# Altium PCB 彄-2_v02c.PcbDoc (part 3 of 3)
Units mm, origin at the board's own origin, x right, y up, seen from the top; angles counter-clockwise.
Board outline 115 x 70 mm, 4 copper layers (Top Layer, Mid-Layer 1, Mid-Layer 2, Bottom Layer), stack 1.49 mm thick; 312 components, 169 nets, 916 pads, 492 vias.
Unrouted connection lines stored in the file: 1.
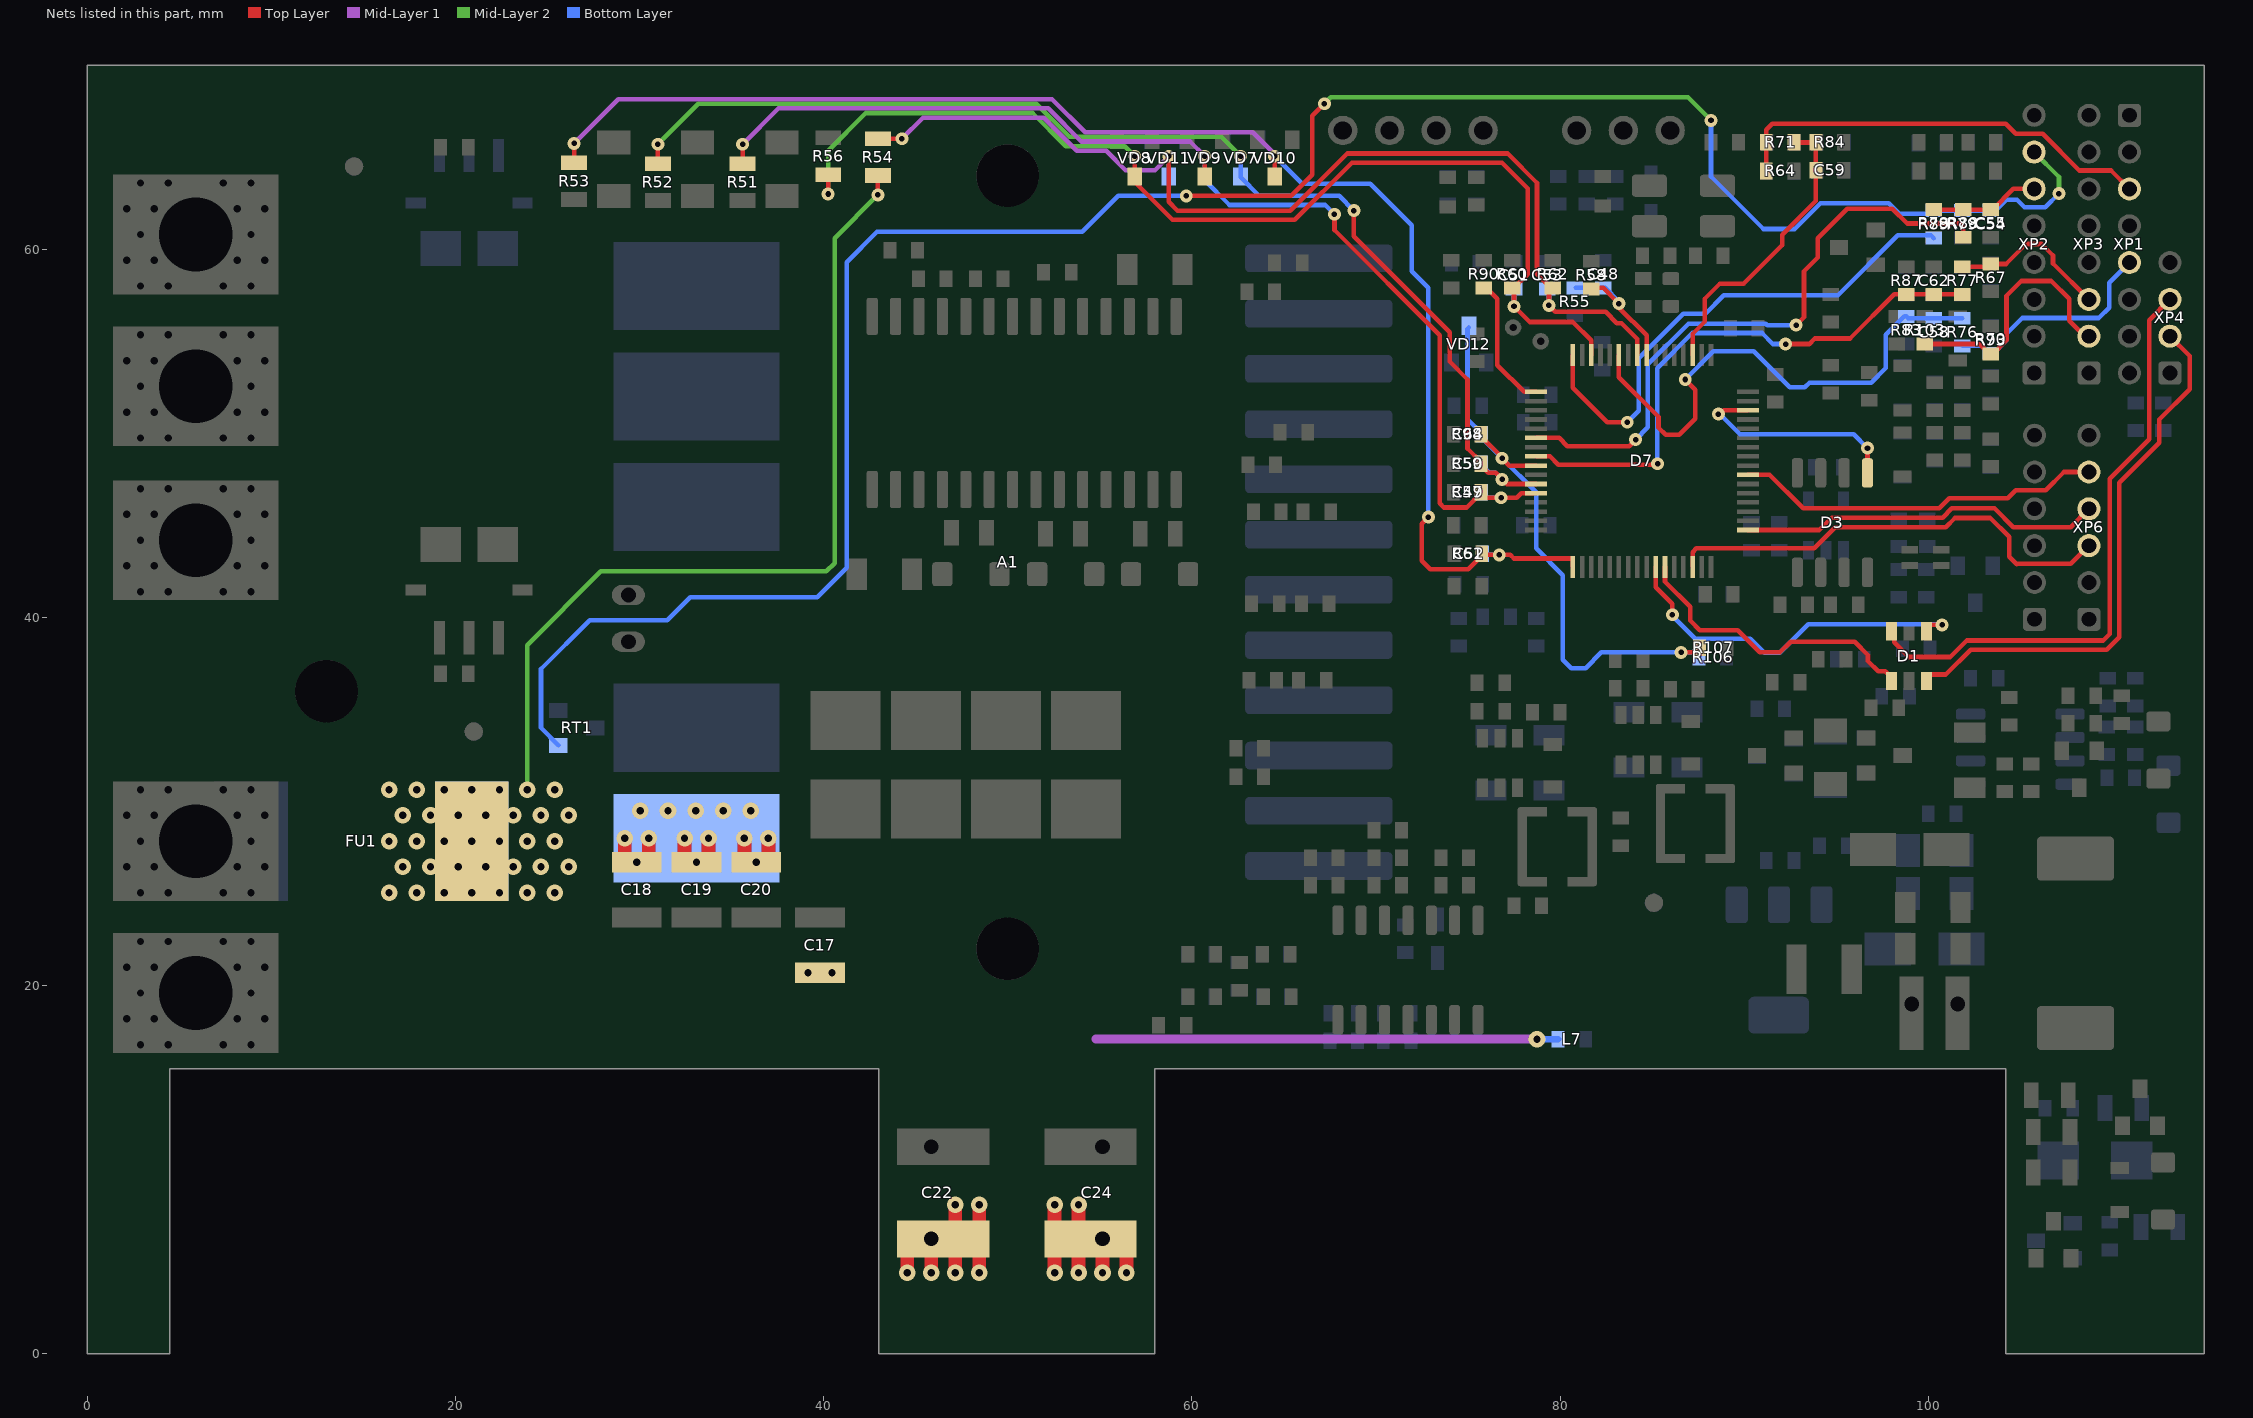
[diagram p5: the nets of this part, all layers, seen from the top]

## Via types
v1: diameter 0.9, hole 0.4, Top Layer to Bottom Layer, 233 vias
v2: diameter 0.7, hole 0.3, Top Layer to Bottom Layer, tented both sides, 184 vias
v3: diameter 0.9, hole 0.4, Top Layer to Bottom Layer, tented both sides, 50 vias
v4: diameter 0.9, hole 0.4, Top Layer to Bottom Layer, tented bottom, 25 vias

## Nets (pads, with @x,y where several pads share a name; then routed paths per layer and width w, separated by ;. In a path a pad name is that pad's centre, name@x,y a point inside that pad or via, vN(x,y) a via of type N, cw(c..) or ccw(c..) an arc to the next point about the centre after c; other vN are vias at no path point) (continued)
SPD2_COS: R93.2 R103.2 XP3.2 | length 13.9
  Top Layer w0.25: R103.2@99.8,54.85 102.8,54.85 103.35,54.3 R93.2@103.4,54.3 103.5,54.3 104.25,55.05 104.25,57.475 105.05,58.275 106.675,58.275 107.65,57.3 107.65,56.125 XP3.2@108.5,55.275
SPD_SW: R64.2 R71.1 XP1.3 | length 23.6
  Top Layer w0.25: R64.2@91.2,64.25 R71.1@91.2,65.8 91.2,66.5 91.525,66.825 104.2,66.825 104.75,66.275 106.209,66.275 108.209,64.275 109.925,64.275 XP1.3@110.925,63.275
SPD_SWU: C59.2 D7.3 R71.2 R84.2 | length 16.3
  Top Layer w0.24: D7.3@87.2,54.25 87.2,55.4 87.85,56.05 87.85,57.3 88.685,58.135 89.985,58.135 92.075,60.225 92.075,60.675
  Top Layer w0.25: 92.075,60.675 92.075,60.796 93.9,62.621 C59.2@93.9,64.3 R84.2@93.9,65.8 R71.2@92.7,65.8
TCK: D7.49 XP6.4 | length 19.8
  Top Layer w0.25: D7.49@90.2,44.75 94.075,44.75 94.75,45.425 100.783,45.425 101.283,45.925 103.6,45.925 104.615,44.91 107.735,44.91 XP6.4@108.725,45.9
TDO: D7.55 XP6.5 | length 19.9
  Top Layer w0.25: D7.55@90.2,47.75 91.375,47.75 93.2,45.925 100.59,45.925 101.14,46.475 104.325,46.475 104.76,46.91 106.385,46.91 107.375,47.9 XP6.5@108.5,47.9
THROTTLE: C58.2 D7.11 R76.2 R83.2 | length 28.9
  Top Layer w0.25: D7.11@83.2,54.25 83.2,53.05 85.35,50.9 85.35,50.3 85.735,49.915 86.465,49.915 87.35,50.8 87.35,52.375 v2(86.8,52.925)
  Bottom Layer w0.25: v2(86.8,52.925) 88.325,54.45 90.524,54.45 92.474,52.5 93.3,52.5 93.55,52.75 96.9,52.75 97.7,53.55 97.7,55.35 98.7,56.35 R83.2@98.8,56.35 98.9,56.25 C58.2@100.3,56.25 R76.2@101.85,56.25
THROTTLE-IN: R70.2 R76.1 XP1.5 | length 12.3
  Bottom Layer w0.25: R76.1@101.85,54.75 102.9,54.75 103.3,54.35 R70.2@103.4,54.35 103.55,54.35 104.25,55.05 104.25,55.4 105.115,56.265 109.265,56.265 109.825,56.825 109.825,58.175 XP1.5@110.925,59.275
TMOTOR1+: C55.2 R78.1 R88.2 XP2.6 | length 5.9
  Top Layer w0.25: R78.1@100.3,62.15 R88.2@101.9,62.15 C55.2@103.4,62.15 103.5,62.15 104.625,63.275 XP2.6@105.75,63.275
TMOTOR1U: D7.22 R88.1 | length 33.7
  Top Layer w0.25: D7.22@78.7,49.75 79.95,49.75 80.4,49.3 83.75,49.3 v2@84,49.55 ; v2(92.825,55.875) 93.25,56.3 93.25,58.8 94,59.55 94,60.6 95.6,62.2 98.05,62.2 98.85,61.4 101.75,61.4 101.9,61.25 R88.1@101.9,60.65
  Bottom Layer w0.25: v2(84.109,49.659) 84.775,50.325 84.775,53.745 86.98,55.95 91.175,55.95 91.25,55.875 v2(92.825,55.875)
TMS: D7.46 XP6.3 | length 25.2
  Top Layer w0.25: D7.46@87.2,42.75 87.2,43.55 87.4,43.75 93.8,43.75 94.95,44.9 100.951,44.9 101.451,45.4 103.375,45.4 104.4,44.375 104.4,43.3 104.8,42.9 104.81,42.91 107.735,42.91 XP6.3@108.725,43.9
TORQUE-IN: R67.2 R77.1 XP3.3 | length 8.7
  Top Layer w0.25: R77.1@101.85,59.05 R67.2@103.25,59.05 ; R67.2@103.4,59.2 104.225,59.2 105.31,60.285 106.15,60.285 106.775,59.66 106.775,59.225 XP3.3@108.725,57.275
TORQUESNS: C62.2 D7.24 R77.2 R87.2 | length 30.7
  Top Layer w0.25: D7.24@78.7,48.75 79.455,48.75 79.905,48.3 85.25,48.3 v2(85.3,48.35) ; v2(92.25,54.85) 93.543,54.85 93.843,55.15 95.75,55.15 98.15,57.55 R87.2@98.8,57.55 R77.2@101.85,57.55
  Bottom Layer w0.25: v2(85.3,48.35) 85.275,48.375 85.275,53.538 87.187,55.45 90.968,55.45 91.568,54.85 v2(92.25,54.85)
TPM1ORM2+: C54.2 R79.1 R89.2 RT1.1 XP2.7 | length 120.6
  Top Layer w0.25: v2(59.7,62.9) 65.4,62.9 66.55,64.05 66.55,67.25 v2(67.2,67.9)
  Mid-Layer 2 w0.25: v2(67.2,67.9) 67.55,68.25 86.95,68.25 v2(88.2,67) ; XP2.7@105.75,65.275 107.1,63.925 v2(107.1,63.025)
  Bottom Layer w0.25: RT1.1@25.6,33.05 24.65,34 24.65,37.2 27.3,39.85 31.5,39.85 32.75,41.1 39.65,41.1 41.25,42.7 41.25,59.3 42.9,60.95 54.05,60.95 56,62.9 v2(59.7,62.9) ; v2(88.2,67) 88.2,63.95 91.05,61.1 92.75,61.1 94.15,62.5 97.85,62.5 98.425,61.925 100.125,61.925 R89.2@100.3,62.1 R79.1@101.85,62.1 C54.2@103.4,62.1 103.639,62.1 104.229,62.69 104.821,62.69 105.226,62.285 106.36,62.285 v2(107.1,63.025)
TPM1ORM2U: D7.16 R89.1 | length 28.1
  Top Layer w0.25: D7.16@80.7,54.25 80.7,52.468 82.568,50.6 v2(83.65,50.6)
  Bottom Layer w0.25: v2(83.65,50.6) 84.275,51.225 84.275,54.075 86.7,56.5 87.9,56.5 88.9,57.5 95.1,57.5 98.35,60.75 100.15,60.75 R89.1@100.3,60.6
TPM2U: D7.17 R90.1 | length 7.5
  Top Layer w0.25: R90.1@75.645,57.9 75.75,57.9 R90.1@75.825,57.825 ; R90.1@75.9,57.9 76,57.9 76.6,57.3 76.6,53.7 78.05,52.25 D7.17@78.7,52.25
TX_CAN: D3.1 D7.62 | length 12
  Top Layer w0.25: v2(88.6,51.05) 88.65,51 88.9,51.25 D7.62@90.2,51.25 ; D3.1@96.7,47.85 v2(96.7,49.2) v2@96.7,49.25
  Bottom Layer w0.25: v2(88.6,51.05) 88.675,51.05 89.775,49.95 95.95,49.95 v2(96.7,49.2)
U-DC: A1.1 C17.2 C18.2 C19.2 C20.2 C22.1 C24.1 FU1.2 L7.1 pad.0@20.9,27.85 R54.1 | length 115.2
  Top Layer w0.25: v2(42.95,62.95) R54.1@42.95,64
  Top Layer w0.75: v1(29.2,28) 29.2,26.701 v1(29.851,26.701) 30.501,26.701 v1@30.501,27.999 ; v1(32.45,28) 32.45,26.701 v1(33.101,26.701) 33.751,26.701 v1@33.751,27.999 ; v1(35.7,28) 35.7,26.701 v1(36.35,26.701) ; v1(36.35,26.701) 37.001,26.701 v1@37.001,27.999 ; v1(44.55,4.401) 44.55,6.25 C22.1@45.85,6.25 ; v1(45.851,4.401) C22.1@45.85,6.25 ; v1(47.151,4.401) v1(47.151,4.401) C22.1@47.152,6.25 ; v1(47.153,8.099) 47.152,8.098 C22.1@47.152,6.25 ; v1(48.452,4.401) v1(48.452,4.401) C22.1@48.453,6.25 ; v1(48.454,8.099) 48.453,8.098 C22.1@48.453,6.25 ; v1(52.548,4.401) 52.547,4.402 C24.1@52.547,6.25 ; v1(52.548,8.099) 52.547,8.098 C24.1@52.547,6.25 ; v1(53.849,4.401) v1(53.849,4.401) C24.1@53.848,6.25 ; v1(53.849,8.099) v1(53.849,8.099) C24.1@53.848,6.25 ; v1(55.149,4.401) C24.1@55.15,6.25 ; v1(56.45,4.401) 56.45,6.25 C24.1@55.15,6.25 ; C22.1@45.85,6.25 C22.1@47.152,6.25 ; C22.1@47.152,6.25 C22.1@48.453,6.25 ; C24.1@52.547,6.25 C24.1@53.848,6.25 ; C24.1@53.848,6.25 C24.1@54.5,6.25 C24.1@55.15,6.25
  Mid-Layer 1 w0.5: 54.8,17.1 v3(78.75,17.1)
  Mid-Layer 2 w0.25: v1(23.9,30.65) 23.9,38.5 27.9,42.5 40.15,42.5 40.6,42.95 40.6,60.6 v2(42.95,62.95)
  Bottom Layer w0.35: v3(78.75,17.1) L7.1@79.9,17.1
  other v1: 39.155,20.712 40.455,20.712 19.4,25.05 20.9,25.05 22.4,25.05 23.9,25.05 25.4,25.05 20.15,26.45 21.65,26.45 23.15,26.45 24.65,26.45 26.15,26.45 19.4,27.85 20.9,27.85 22.4,27.85 23.9,27.85 25.4,27.85 30.5,28 33.75,28 37,28 20.15,29.25 21.65,29.25 23.15,29.25 24.65,29.25 26.15,29.25 30.05,29.5 31.55,29.5 33.05,29.5 34.55,29.5 36.05,29.5 19.4,30.65 20.9,30.65 22.4,30.65 25.4,30.65
  other v4: 16.4,25.05 17.9,25.05 17.15,26.45 18.65,26.45 16.4,27.85 17.9,27.85 17.15,29.25 18.65,29.25 16.4,30.65 17.9,30.65
U-DCA: C53.1 D7.9 R54.2 R62.2 VD11.3 | length 57.5
  Top Layer w0.25: R54.2@42.95,66 v2(44.25,66) ; v2@58.75,64.85 58.75,62.575 59.225,62.1 65.35,62.1 68.45,65.2 77.15,65.2 78.75,63.6 78.75,58.65 R62.2@79.5,57.9 ; R62.2@79.4,57.8 v2(79.4,56.95) 79.75,56.6 82.475,56.6 83.088,55.988 83.338,55.988 84.2,55.125 D7.9@84.2,54.25
  Mid-Layer 1 w0.25: v2(44.25,66) 45.4,67.15 51.95,67.15 53.75,65.35 55.35,65.35 56.4,64.3 58,64.3 v2(58.75,65.05)
  Bottom Layer w0.25: VD11.3@58.75,63.95 v2(58.75,65.05) ; v2(79.4,56.95) C53.1@79.4,57.85
U-DCERR: C48.1 D7.8 R55.1 R58.2 | length 8.3
  Top Layer w0.25: R58.2@81.45,57.9 82.35,57.9 v2(83.2,57.05) 83.2,56.832 84.7,55.332 D7.8@84.7,54.25
  Bottom Layer w0.25: R55.1@80.85,57.9 C48.1@82.35,57.9 82.45,57.9 83.2,57.15 v2(83.2,57.05)
U-UA: C49.1 D7.28 R51.2 R57.2 VD9.3 | length 63.1
  Top Layer w0.25: R51.2@35.6,64.65 v2(35.6,65.7) ; VD9.3@60.7,63.95 v2(60.7,65.05) ; v2@67.75,61.875 67.75,61.043 73.475,55.318 73.475,46.195 73.695,45.975 74.925,45.975 R57.2@75.7,46.75 ; R57.2@75.7,46.5 v2(76.8,46.5) 77.65,46.5 77.9,46.75 D7.28@78.7,46.75
  Mid-Layer 1 w0.25: v2(35.6,65.7) 37.55,67.65 52.2,67.65 54,65.85 59.9,65.85 v2(60.7,65.05)
  Bottom Layer w0.25: v2(60.7,65.05) 60.7,63.75 62.05,62.4 67.25,62.4 v2(67.75,61.9) ; C49.1@75.75,46.5 v2(76.8,46.5)
U-VA: C50.1 D7.27 R52.2 R59.2 VD7.3 | length 64.4
  Top Layer w0.25: R52.2@31,64.65 v2(31,65.7) ; v2(68.8,62.1) 68.8,60.7 74,55.5 74,53.9 74.975,52.925 74.975,49.175 75.7,48.45 75.7,48.4 R59.2@75.725,48.375 ; R59.2@75.7,48.35 75.7,48.25 76.1,47.85 76.5,47.85 v2(76.85,47.5) 77.1,47.25 D7.27@78.7,47.25
  Mid-Layer 2 w0.25: v2(31,65.7) 33.2,67.9 51.557,67.9 53.357,66.1 61.6,66.1 v2(62.65,65.05)
  Bottom Layer w0.25: VD7.3@62.65,63.9 63.65,62.9 68,62.9 v2(68.8,62.1) ; VD7.3@62.65,63.95 v2(62.65,65.05) ; C50.1@75.75,48.35 75.75,48.25 76.145,47.855 76.495,47.855 v2(76.85,47.5) ; C50.1@75.75,48.4 C50.1@75.775,48.375
U-WA: C52.1 D7.33 R53.2 R61.2 VD10.3 | length 80.4
  Top Layer w0.25: R53.2@26.45,64.7 v2(26.45,65.75) ; VD10.3@64.5,63.95 v2(64.5,65.05) ; v2(72.85,45.45) 72.5,45.1 72.5,43.075 72.95,42.625 75.025,42.625 75.75,43.35 R61.2@75.75,43.45 ; R61.2@75.8,43.4 v2(76.7,43.4) 77.3,43.4 77.5,43.2 80.7,43.2 D7.33@80.7,42.75
  Mid-Layer 1 w0.25: v2(26.45,65.75) 28.85,68.15 52.407,68.15 54.207,66.35 63.3,66.35 64.5,65.15 v2(64.5,65.05)
  Bottom Layer w0.25: v2(64.5,65.05) 66,63.55 69.7,63.55 71.95,61.3 71.95,58.8 72.85,57.9 v2(72.85,45.45) ; C52.1@75.85,43.4 v2(76.7,43.4)
UART_RX: D1.4 D7.43 | length 16.5
  Top Layer w0.25: D7.43@85.7,42.75 85.7,41.95 87.063,40.587 87.063,39.837 87.6,39.3 89.65,39.3 90.85,38.1 91.95,38.1 92.525,38.675 96,38.675 96.725,37.95 96.725,37.625 97.275,37.075 97.675,37.075 D1.4@98.1,36.65
UART_RXI: D1.3 XP4.3 | length 32.7
  Top Layer w0.25: D1.3@98,39.25 98.15,39.1 98.15,38.65 98.95,37.85 101.2,37.85 102.1,38.75 109.5,38.75 109.85,39.1 109.85,47.525 112,49.675 112,56.15 XP4.3@113.125,57.275
UART_TX: D1.1 D7.42 | length 20
  Top Layer w0.25: D7.42@85.2,42.75 85.2,41.65 86.1,40.75 v2(86.1,40.15) ; D1.1@99.9,39.6 v2(100.75,39.6)
  Bottom Layer w0.25: v2(86.1,40.15) 86.1,40.1 87.35,38.85 90.325,38.85 91.1,38.075 91.925,38.075 93.475,39.625 100.725,39.625 v2(100.75,39.6)
UART_TXO: D1.6 XP4.2 | length 30
  Top Layer w0.25: D1.6@99.9,36.55 99.9,36.9 100.957,36.9 102.307,38.25 109.693,38.25 110.365,38.922 110.365,47.315 112.55,49.5 112.55,50.75 114.2,52.4 114.2,54.2 XP4.2@113.125,55.275
UINT-ERR: C64.1 D7.25 R98.2 R106.1 R107.1 VD12.3 | length 32.9
  Top Layer w0.25: R98.2@75.7,49.85 76.85,48.7 v2(76.85,48.65) 77.25,48.25 D7.25@78.7,48.25 ; v2(86.575,38.1) 87.325,38.1 R107.1@87.575,38.35
  Bottom Layer w0.25: VD12.3@75.05,55.75 74.975,55.675 74.975,50.775 C64.1@75.75,50 ; C64.1@75.75,49.75 v2(76.85,48.65) 78.7,46.8 78.7,43.75 80.15,42.3 80.15,37.7 80.6,37.25 81.4,37.25 82.25,38.1 v2(86.575,38.1) 87.3,38.1 R106.1@87.55,37.85 ; C64.1@75.75,49.85 C64.1@75.75,49.95
VIRTGND: C51.1 D7.14 R56.2 R60.2 VD8.3 | length 60.8
  Top Layer w0.25: v2(40.25,63) R56.2@40.25,64.05 ; VD8.3@56.9,63.65 58.95,61.6 65.6,61.6 68.7,64.7 76.85,64.7 78.25,63.3 78.25,58.65 R60.2@77.5,57.9 ; VD8.3@56.9,63.85 VD8.3@56.9,63.95 v2(56.9,65.05) ; R60.2@77.4,57.9 R60.2@77.5,57.9 ; R60.2@77.55,57.9 R60.2@77.65,57.9 ; D7.14@81.7,54.25 81.7,55.05 80.7,56.05 78.35,56.05 v2(77.5,56.9) R60.2@77.5,57.9
  Mid-Layer 2 w0.25: v2(40.25,63) 40.25,65.35 42.3,67.4 51.35,67.4 53.15,65.6 56.35,65.6 v2(56.9,65.05)
  Bottom Layer w0.25: v2(77.5,56.9) C51.1@77.5,57.85
pads on no net: A1.0 BQ1.1 BQ1.3 D3.5 D4.17 D4.21 D4.25 D5.4 D5.7 D6.4 D6.7 D7.50 D8.14 REP1.0 REP2.0 REP3.0 REP4.0 REP5.0 REP6.0 RT1.3

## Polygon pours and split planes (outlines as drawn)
GND on Bottom Layer "Bottom Layer-No Net" (solid, remove dead copper, pour order 1081): 73 vertices, not listed, extent 67.091,26.9 114.25,69.1
5V on Bottom Layer "Bottom Layer-No Net" (solid, pour order 1060): 22 vertices, not listed, extent 84.25,29 89.651,37.871
GND on Bottom Layer "Bottom Layer-No Net" (solid, pour order 1056): 84.15,32.85 86.8,32.85 ccw(c86.8,34) 87.95,34 87.95,35.9 ccw(c87.2,35.9) 87.2,36.65 84.25,36.65 cw(c84.25,37.1) 83.8,37.1 83.8,37.6 ccw(c83.55,37.6) 83.55,37.85 82.9,37.85 ccw(c82.9,37.6) 82.65,37.6 82.65,33.15 ccw(c82.95,33.15) 82.95,32.85
GND on Bottom Layer "Bottom Layer-No Net" (solid, pour order 1052): 78.15,31.55 78.914,31.55 ccw(c78.914,33.086) 80.45,33.086 80.45,34.85 ccw(c79.8,34.85) 79.8,35.5 76.7,35.5 cw(c76.7,36.05) 76.15,36.05 76.15,37.5 ccw(c75.85,37.5) 75.85,37.8 74.65,37.8 74.65,36.6 74.65,31.9 ccw(c75,31.9) 75,31.55
3V3D on Bottom Layer "Bottom Layer-No Net" (solid, pour order 1048): 21 vertices, not listed, extent 76.95,27 82.15,37.85
NetC74_2 on Bottom Layer "Bottom Layer-No Net" (solid, pour order 1044): 18 vertices, not listed, extent 79.5,16.45 93.95,25.5
NetC72_1 on Bottom Layer "Bottom Layer-No Net" (solid, pour order 1051): 18 vertices, not listed, extent 100.55,21.1 111.95,28.35
12V on Bottom Layer "Bottom Layer-No Net" (solid, pour order 1050): 100.95,20.5 102.612,20.5 cw(c102.612,20.145) 102.967,20.145 102.967,19.883 ccw(c103.75,19.883) 103.75,19.1 112.6,19.1 cw(c112.6,18.75) 112.95,18.75 112.95,16.65 cw(c112.7,16.65) 112.7,16.4 101.1,16.4 cw(c101.1,16.8) 100.7,16.8 100.7,20.25 cw(c100.95,20.25) 100.95,20.5
GND on Bottom Layer "Bottom Layer-No Net" (solid, pour order 1037): 99.85,20.2 99.85,22.7 ccw(c99.45,22.7) 99.45,23.1 96.85,23.1 ccw(c96.85,21.4) 95.15,21.4 95.15,18 ccw(c95.5,18) 95.5,17.65 99.3,17.65 ccw(c99.3,18.2) 99.85,18.2
NetR117_1 on Bottom Layer "Bottom Layer-No Net" (solid, pour order 1043): 21 vertices, not listed, extent 93.6,23.4 99.55,28.4
L3 on Bottom Layer "Bottom Layer-No Net" (solid, pour order 1036): 20 vertices, not listed, extent 21.1,55.5 39.4,61.15
PH_B on Bottom Layer "Bottom Layer-No Net" (solid, pour order 1042): 17 vertices, not listed, extent 1.05,48.95 39.4,56.15
PH_C on Bottom Layer "Bottom Layer-No Net" (solid, pour order 1047): 29 vertices, not listed, extent 1.05,55.5 20.4,64.4
L1 on Bottom Layer "Bottom Layer-No Net" (solid, pour order 1049): 20 vertices, not listed, extent 21.1,42.85 39.4,48.5
PH_A on Bottom Layer "Bottom Layer-No Net" (solid, pour order 1055): 26 vertices, not listed, extent 1.049,40.55 20.4,48.5
NetFU1_1 on Bottom Layer "Bottom Layer-No Net" (solid, pour order 1063): 9.3,31.45 13.6,31.45 cw(c13.6,30.8) 14.25,30.8 14.25,24.9 cw(c13.6,24.9) 13.6,24.25 1.65,24.25 cw(c1.65,24.85) 1.05,24.85 1.05,30.85 cw(c1.65,30.85) 1.65,31.45
U-DC on Bottom Layer "Bottom Layer-No Net" (solid, pour order 1035): 22 vertices, not listed, extent 15.5,2.55 57.504,31.5
PGND on Bottom Layer "Bottom Layer-No Net" (solid, pour order 1041): 14.25,22.15 14.25,22.9 ccw(c13.65,22.9) 13.65,23.5 1.8,23.5 ccw(c1.8,22.75) 1.05,22.75 1.05,16.65 ccw(c1.7,16.65) 1.7,16 13.55,16 ccw(c13.55,16.7) 14.25,16.7
SH+ on Bottom Layer "Bottom Layer-No Net" (solid, pour order 1046): 49.1,39.45 55.7,39.45 cw(c55.7,37.1) 58.05,37.1 58.05,25.05 ccw(c59,25.05) 59,24.1 60.164,24.1 ccw(c60.164,25.197) 61.261,25.197 61.261,59.751 ccw(c60.65,59.751) 60.65,60.362 44.195,60.362 ccw(c44.195,57.901) 41.734,57.901 41.734,40.644 ccw(c42.927,40.644) 42.927,39.452
NetL5_1 on Bottom Layer "Bottom Layer-No Net" (solid, pour order 1054): 97.45,35.05 97.45,36.25 98.95,36.25 99.35,36.25 99.35,34.15 99.35,31.9 cw(c98.05,31.9) 98.05,30.6 96.35,30.6 cw(c96.35,31.05) 95.9,31.05 95.9,34.9 cw(c96.05,34.9) 96.05,35.05
SH+ on Bottom Layer "Bottom Layer-No Net" (solid, pour order 1034): 21 vertices, not listed, extent 28.55,31.5 57.25,38.9
AGND on Bottom Layer "Bottom Layer-No Net" (solid, pour order 1040): 28.2,34.3 28.2,37.05 ccw(c27.95,37.05) 27.95,37.3 27.7,37.3 ccw(c27.7,36.55) 26.95,36.55 26.95,32.25 ccw(c27.7,32.25) 27.7,31.5 28.05,31.5 ccw(c28.05,31.65) 28.2,31.65
no net on Top Layer "Top Layer-No Net" (solid, pour order 1119): 16.713,30.45 13.087,30.45 13.087,28.95 16.713,28.95
NetR112_2 on Top Layer "Top Layer-No Net" (solid, pour order 1121): 107.7,15.55 ccw(c107.7,14.65) 106.8,14.65 106.8,13.6 ccw(c107.05,13.6) 107.05,13.35 111.35,13.35 ccw(c111.35,13.95) 111.95,13.95 111.95,15.2 ccw(c111.6,15.2) 111.6,15.55
GND on Top Layer "Bottom Layer-No Net" (solid, remove dead copper, pour order 1079): 73 vertices, not listed, extent 67.091,26.9 114.25,69.1
no net on Top Layer "Top Layer-No Net" (solid, pour order 1117): 16.713,26.7 13.087,26.7 13.087,25.2 16.713,25.2
NetC74_2 on Top Layer "Bottom Layer-No Net" (solid, pour order 1062): 93.95,20.45 93.95,22 ccw(c93.5,22) 93.5,22.45 80.15,22.45 ccw(c80.15,21.8) 79.5,21.8 79.5,16.85 ccw(c79.9,16.85) 79.9,16.45 93.419,16.45 ccw(c93.419,16.989) 93.959,16.989
NetC72_1 on Top Layer "Bottom Layer-No Net" (solid, pour order 1077): 105.9,25.4 111.25,25.4 ccw(c111.25,26.1) 111.95,26.1 111.95,27.75 ccw(c111.35,27.75) 111.35,28.35 103.85,28.35 ccw(c103.85,27.85) 103.35,27.85 103.35,26.15 ccw(c104.1,26.15) 104.1,25.4
GND on Top Layer "Bottom Layer-No Net" (solid, pour order 1073): 95.1,22.8 95.1,16.667 ccw(c95.352,16.667) 95.352,16.415 99.85,16.415 99.85,20 99.85,25.2 ccw(c99.6,25.2) 99.6,25.45 95.5,25.45 ccw(c95.5,25.05) 95.1,25.05
NetC82_1 on Top Layer "Bottom Layer-No Net" (solid, pour order 1066): 18 vertices, not listed, extent 77.4,25.4 80.1,31.25
5V on Top Layer "Bottom Layer-No Net" (solid, pour order 1059): 19 vertices, not listed, extent 87.9,26.65 89.65,38.2
NetC81_1 on Top Layer "Bottom Layer-No Net" (solid, pour order 1053): 18 vertices, not listed, extent 84.9,26.65 87.6,32.5
12V on Top Layer "Bottom Layer-No Net" (solid, pour order 1045): 101.45,16.4 112.7,16.4 ccw(c112.7,16.65) 112.95,16.65 112.95,18.75 ccw(c112.6,18.75) 112.6,19.1 103.65,19.1 cw(c103.65,19.9) 102.85,19.9 102.85,25.4 ccw(c102.8,25.4) 102.8,25.45 100.8,25.45 ccw(c100.8,25.35) 100.7,25.35 100.7,16.5 ccw(c100.8,16.5) 100.8,16.4
GND on Top Layer "Bottom Layer-No Net" (solid, pour order 1039): 19 vertices, not listed, extent 82.15,32.8 87.75,35.2
GND on Top Layer "Bottom Layer-No Net" (solid, pour order 1038): 19 vertices, not listed, extent 74.65,31.55 80.25,33.95
3V3D on Top Layer "Bottom Layer-No Net" (solid, pour order 1058): 80.4,28.85 80.4,30.195 cw(c81.524,30.195) 80.729,30.99 ccw(c79.713,32.006) 81.15,32.006 81.15,32.15 82.15,32.15 82.15,25.593 cw(c81.954,25.593) 81.954,25.397 80.402,25.397 80.402,26.371 ccw(c80.402,27.131) 81.161,27.131 81.161,27.55 81.161,27.968 ccw(c80.4,27.968) 80.4,28.729
L3 on Top Layer "Bottom Layer-No Net" (solid, pour order 1069): 20 vertices, not listed, extent 21.1,55.5 39.4,61.15
PH_C on Top Layer "Bottom Layer-No Net" (solid, pour order 1072): 29 vertices, not listed, extent 1.05,55.5 20.4,64.4
PH_B on Top Layer "Bottom Layer-No Net" (solid, pour order 1076): 17 vertices, not listed, extent 1.05,48.95 39.4,56.15
L1 on Top Layer "Bottom Layer-No Net" (solid, pour order 1080): 20 vertices, not listed, extent 21.1,42.85 39.4,48.5
PH_A on Top Layer "Bottom Layer-No Net" (solid, pour order 1083): 26 vertices, not listed, extent 1.049,40.55 20.4,48.5
NetFU1_1 on Top Layer "Bottom Layer-No Net" (solid, pour order 1086): 9.3,31.45 13.6,31.45 cw(c13.6,30.8) 14.25,30.8 14.25,24.9 cw(c13.6,24.9) 13.6,24.25 1.65,24.25 cw(c1.65,24.85) 1.05,24.85 1.05,30.85 cw(c1.65,30.85) 1.65,31.45
U-DC on Top Layer "Bottom Layer-No Net" (solid, pour order 1090): 18 vertices, not listed, extent 15.497,24.2 37.85,31.5
PGND on Top Layer "Bottom Layer-No Net" (solid, pour order 1057): 23 vertices, not listed, extent 1.069,2.55 57.504,31.207
SH+ on Top Layer "Bottom Layer-No Net" (solid, pour order 1061): 21 vertices, not listed, extent 26.95,31.494 57.25,38.91
NetL6_1 on Top Layer "Bottom Layer-No Net" (solid, pour order 1065): 93.2,30.6 90.35,30.6 cw(c90.35,31) 89.95,31 89.95,36.65 cw(c90.6,36.65) 90.6,37.3 92.8,37.3 cw(c92.8,36.9) 93.2,36.9
AGND on Mid-Layer 1 "Bottom Layer-No Net" (solid, pour order 1075): 56 vertices, not listed, extent 55.05,19.25 84.8,69.1
GND on Mid-Layer 1 "Bottom Layer-No Net" (solid, pour order 1071): 60 vertices, not listed, extent 71.4,4.745 114.306,37.35
NetC74_2 on Mid-Layer 1 "Bottom Layer-No Net" (solid, pour order 1068): 93.95,20.45 93.95,22 ccw(c93.5,22) 93.5,22.45 80.15,22.45 ccw(c80.15,21.8) 79.5,21.8 79.5,16.85 ccw(c79.9,16.85) 79.9,16.45 93.419,16.45 ccw(c93.419,16.989) 93.959,16.989
AGND on Mid-Layer 1 "Bottom Layer-No Net" (solid, pour order 1064): 55.55,69.1 23,69.1 21.9,68 52.314,68 cw(c52.314,66.464) 53.4,67.55 53.406,67.544 ccw(c55.202,69.34) 55.202,66.8 55.55,66.8
L3 on Mid-Layer 1 "Bottom Layer-No Net" (solid, pour order 1093): 20 vertices, not listed, extent 21.1,55.5 39.4,61.15
PH_B on Mid-Layer 1 "Bottom Layer-No Net" (solid, pour order 1096): 17 vertices, not listed, extent 1.05,48.95 39.4,56.15
PH_C on Mid-Layer 1 "Bottom Layer-No Net" (solid, pour order 1099): 29 vertices, not listed, extent 1.05,55.5 20.4,64.4
L1 on Mid-Layer 1 "Bottom Layer-No Net" (solid, pour order 1102): 20 vertices, not listed, extent 21.1,42.85 39.4,48.5
PH_A on Mid-Layer 1 "Bottom Layer-No Net" (solid, pour order 1103): 26 vertices, not listed, extent 1.049,40.55 20.4,48.5
NetFU1_1 on Mid-Layer 1 "Bottom Layer-No Net" (solid, pour order 1104): 9.3,31.45 13.6,31.45 cw(c13.6,30.8) 14.25,30.8 14.25,24.9 cw(c13.6,24.9) 13.6,24.25 1.65,24.25 cw(c1.65,24.85) 1.05,24.85 1.05,30.85 cw(c1.65,30.85) 1.65,31.45
U-DC on Mid-Layer 1 "Bottom Layer-No Net" (solid, pour order 1067): 22 vertices, not listed, extent 15.5,2.55 57.504,31.5
PGND on Mid-Layer 1 "Bottom Layer-No Net" (solid, pour order 1070): 14.25,22.15 14.25,22.9 ccw(c13.65,22.9) 13.65,23.5 1.8,23.5 ccw(c1.8,22.75) 1.05,22.75 1.05,16.65 ccw(c1.7,16.65) 1.7,16 13.55,16 ccw(c13.55,16.7) 14.25,16.7
SH+ on Mid-Layer 1 "Bottom Layer-No Net" (solid, pour order 1074): 21 vertices, not listed, extent 26.95,31.494 57.25,38.91
GND on Mid-Layer 1 "Bottom Layer-No Net" (solid, pour order 1078): 71.05,20.85 71.05,17.85 70.8,17.85 58.35,17.85 cw(c58.35,18.15) 58.05,18.15 58.05,37.1 ccw(c55.7,37.1) 55.7,39.45 43.1,39.45 cw(c43.1,40.8) 41.75,40.8 41.75,58.3 cw(c44,58.3) 44,60.55 69.15,60.55 cw(c69.15,58.65) 71.05,58.65
GND on Mid-Layer 1 "Bottom Layer-No Net" (solid, pour order 1082): 58 vertices, not listed, extent 67.089,26.95 114.257,69.109
NetL5_1 on Mid-Layer 1 "Bottom Layer-No Net" (solid, pour order 1085): 99.35,33.6 99.35,31.9 cw(c98.05,31.9) 98.05,30.6 93.2,30.6 cw(c93.2,30.9) 92.9,30.9 92.9,32.198 cw(c95.44,32.198) 93.644,33.994 93.65,34 93.999,34.349 cw(c95.45,32.898) 95.45,34.95 98.95,34.95 cw(c98.95,34.55) 99.35,34.55
NetL6_1 on Mid-Layer 1 "Bottom Layer-No Net" (solid, pour order 1088): 90,33.15 90,30.9 ccw(c90.3,30.9) 90.3,30.6 91.8,30.6 ccw(c91.8,30.8) 92,30.8 92,34.725 ccw(c91.825,34.725) 91.825,34.9 90.375,34.9 ccw(c90.375,34.525) 90,34.525
GND on Mid-Layer 2 "Top Layer-No Net" (solid, pour order 1115): 114.275,65.9 114.275,38.6 cw(c113.45,38.6) 113.45,37.775 106.45,37.775 cw(c106.45,38.65) 105.575,38.65 105.575,59.698 ccw(c103.035,59.698) 104.831,61.494 104.6,61.725 cw(c105.505,62.63) 104.225,62.63 104.225,68.025 cw(c105.3,68.025) 105.3,69.1 113.265,69.1 cw(c113.265,68.1) 114.265,68.1
5V on Mid-Layer 2 "Top Layer-No Net" (solid, pour order 1113): 53 vertices, not listed, extent 82.95,26.95 105.303,68.38
3V3A on Mid-Layer 2 "Bottom Layer-No Net" (solid, pour order 1098): 56.25,67.15 54.802,67.15 cw(c54.802,69.69) 53.006,67.894 52.95,67.95 52.595,68.305 ccw(c51.4,67.11) 51.4,68.8 51.4,69.1 56.25,69.1
3V3D on Mid-Layer 2 "Bottom Layer-No Net" (solid, pour order 1095): 77 vertices, not listed, extent 67.1,26.95 101.511,68.406
3V3A on Mid-Layer 2 "Bottom Layer-No Net" (solid, pour order 1092): 56 vertices, not listed, extent 55.05,19.25 84.8,69.1
12V on Mid-Layer 2 "Bottom Layer-No Net" (solid, pour order 1087): 44 vertices, not listed, extent 77.1,16.383 114.281,37.35
NetC74_2 on Mid-Layer 2 "Bottom Layer-No Net" (solid, pour order 1084): 93.95,20.45 93.95,22 ccw(c93.5,22) 93.5,22.45 80.15,22.45 ccw(c80.15,21.8) 79.5,21.8 79.5,16.85 ccw(c79.9,16.85) 79.9,16.45 93.419,16.45 ccw(c93.419,16.989) 93.959,16.989
L3 on Mid-Layer 2 "Bottom Layer-No Net" (solid, pour order 1105): 20 vertices, not listed, extent 21.1,55.5 39.4,61.15
PH_B on Mid-Layer 2 "Bottom Layer-No Net" (solid, pour order 1106): 17 vertices, not listed, extent 1.05,48.95 39.4,56.15
PH_C on Mid-Layer 2 "Bottom Layer-No Net" (solid, pour order 1107): 29 vertices, not listed, extent 1.05,55.5 20.4,64.4
L1 on Mid-Layer 2 "Bottom Layer-No Net" (solid, pour order 1108): 20 vertices, not listed, extent 21.1,42.85 39.4,48.5
PH_A on Mid-Layer 2 "Bottom Layer-No Net" (solid, pour order 1109): 26 vertices, not listed, extent 1.049,40.55 20.4,48.5
U-DC on Mid-Layer 2 "Bottom Layer-No Net" (solid, pour order 1110): 18 vertices, not listed, extent 15.497,24.2 37.85,31.5
NetFU1_1 on Mid-Layer 2 "Bottom Layer-No Net" (solid, pour order 1111): 9.3,31.45 13.6,31.45 cw(c13.6,30.8) 14.25,30.8 14.25,24.9 cw(c13.6,24.9) 13.6,24.25 1.65,24.25 cw(c1.65,24.85) 1.05,24.85 1.05,30.85 cw(c1.65,30.85) 1.65,31.45
PGND on Mid-Layer 2 "Bottom Layer-No Net" (solid, pour order 1089): 23 vertices, not listed, extent 1.069,2.55 57.504,31.207
GND on Mid-Layer 2 "Bottom Layer-No Net" (solid, pour order 1091): 58.05,26.65 58.05,16.8 ccw(c58.55,16.8) 58.55,16.3 70.55,16.3 ccw(c70.55,16.8) 71.05,16.8 71.05,58.65 ccw(c69.15,58.65) 69.15,60.55 44.056,60.55 ccw(c44.056,58.251) 41.757,58.251 41.757,40.743 ccw(c43.05,40.743) 43.05,39.45 55.711,39.45 cw(c55.711,37.1) 58.061,37.1
SH+ on Mid-Layer 2 "Bottom Layer-No Net" (solid, pour order 1094): 21 vertices, not listed, extent 26.95,31.494 57.25,38.91
NetL6_1 on Mid-Layer 2 "Bottom Layer-No Net" (solid, pour order 1097): 93.55,30.6 96.2,30.6 ccw(c96.2,31.05) 96.65,31.05 96.65,33.125 ccw(c94.888,33.288) 95.05,35.05 90.6,35.05 ccw(c90.6,34.45) 90,34.45 90,31.05 ccw(c90.45,31.05) 90.45,30.6

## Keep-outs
Keep-Out Layer:
  circle w0.15: c13,36 r2.2
  circle w0.15: c50,22 r2.5
  circle w0.15: c50,64 r2.5
  lines w0.25: 43,0 58,0 58,2 43,2 43,0 ; 104.2,0 104.2,2 115,2 115,0 104.2,0

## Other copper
Top Layer:
  pour cut-out: 0,68 0,70 115,70 115,68
  pour cut-out: 50,17.3 cw(c50,22) 45.3,22 cw(c50,22) 50,26.7 cw(c50,22) 54.7,22 cw(c50,22)
  pour cut-out: 13,31.5 ccw(c13,36) 17.5,36 ccw(c13,36) 13,40.5 ccw(c13,36) 8.5,36 ccw(c13,36)
  pour cut-out: 40.25,61 40.35,60.9 40.35,58.9 39.45,58.9 39.4,58.85 39.4,59.2 ccw(c38.5,59.2) 38.5,60.1 28.084,60.1 ccw(c28.084,59.693) 27.796,59.981 cw(c28.027,60.212) 27.7,60.212 27.7,61
  text "Top Layer" at 51.05,75.075 h5
  text "2" at 162.2,-180.6 h5
Mid-Layer 1:
  text "Middle-Layer1" at 47.725,75.15 h5
  text "3" at 162.2,-180.6 h5
Mid-Layer 2:
  text "Middle-Layer2" at 47.725,75.15 h5
  text "4" at 162.2,-180.6 h5
Bottom Layer:
  pour cut-out: 0,68 0,70 115,70 115,68
  pour cut-out: 96.25,23.6 cw(c97.25,23.6) 98.25,23.6
  text "Bottom Layer" at 69.725,75.175 h5
Multi-Layer:
  pour cut-out: 111.925,25.345 cw(c111.925,24.295) 112.975,24.295 112.975,19.845 cw(c112.325,19.845) 112.325,19.195 103.925,19.195 cw(c103.925,20.145) 102.975,20.145 102.975,24.545 cw(c103.775,24.545) 103.775,25.345

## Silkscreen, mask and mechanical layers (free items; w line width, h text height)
Top Overlay:
  circle w0.2: c13,36 r4.5
  lines w0.15: 66.7,27.8 68.65,27.8 69.25,27.2 ; 93.2,49.8 96.7,49.8 97.8,50.9 ; 94.9,22.85 97.6,22.85 97.85,22.6 ; 95.85,56.95 99.15,56.95 99.25,56.85 ; 96,54.25 99.3,54.25 100.1,53.45 ; 102.6,50.95 103.05,50.5 103.9,50.5
  lines w0.2: 108.425,12.9 108.7,13.175 108.7,14.475 109.625,15.4 112.75,15.4
  text "Top side components" at 40.575,81.825 h5
  text "8" at 107,66.85 h1.5
  text "1" at 112,66.75 h1.5
  text "2" at 112,64.85 h1.5
  text "7" at 107,64.75 h1.5
  text "6" at 106.975,63.175 h1.5
  text "3" at 111.95,62.75 h1.5
  text "..." at 112.3,61.2 h1.5 r90
  text "5" at 106.95,60.8 h1.5
  text "C" at 12.275,59.025 h2.5
  text "4" at 106.85,58.85 h1.5
  text "4" at 114.05,58.85 h1.5
  text "3" at 114.1,56.85 h1.5
  text "3" at 106.95,56.75 h1.5
  text "2" at 114.1,54.85 h1.5
  text "2" at 106.95,54.8 h1.5
  text "1" at 114.15,52.85 h1.5
  text "1" at 107,52.8 h1.5
  text "B" at 12.325,51.275 h2.5
  text "5" at 106.975,47.475 h1.5
  text "4" at 106.875,45.525 h1.5
  text "3" at 106.975,43.425 h1.5
  text "A" at 12.125,43.05 h2.5
  text "2" at 106.975,41.475 h1.5
  text "+DC" at 13.15,28.525 h2.5
  text "GND" at 13.35,20.275 h2.5
  text "B&E" at 82.05,19.375 h3
  text "INVERTER" at 82.1,17.65 h1.5
Bottom Overlay:
  lines w0.15: 95.7,50.65 99.55,50.65 99.65,50.75 ; 97.281,61.373 99.227,61.373 99.45,61.15 99.45,60.2 99.85,59.8 101.55,59.8 101.7,59.65 ; 97.7,59.95 99.3,59.95 99.65,59.6 ; 102.6,56.4 102.8,56.6 104.85,56.6 ; 108.95,26.75 108.95,31.75 109.15,31.95
  text "Bottom side components" at 77.275,81.75 h5
  text "PAS" at 109.625,68.7 h1.5
  text "Control" at 113.925,68.425 h1.5
  text "Hall" at 106.5,68.4 h1.5
  text "8" at 107.425,66.875 h1.5
  text "1" at 112.425,66.675 h1.5
  text "7" at 107.425,64.775 h1.5
  text "2" at 112.425,64.775 h1.5
  text "6" at 107.525,63.175 h1.5
  text "3" at 112.475,62.675 h1.5
  text "..." at 112.125,61.125 h1.5 r270
  text "5" at 107.475,60.825 h1.5
  text "UART" at 113.2,60.65 h1.5 r270
  text "4" at 107.575,58.875 h1.5
  text "4" at 114.625,58.825 h1.5
  text "3" at 114.575,56.825 h1.5
  text "3" at 107.475,56.775 h1.5
  text "2" at 107.475,54.825 h1.5
  text "2" at 114.575,54.825 h1.5
  text "1" at 107.425,52.825 h1.5
  text "1" at 114.525,52.825 h1.5
  text "6" at 107.475,49.425 h1.5
  text "5" at 107.475,47.425 h1.5
  text "4" at 107.575,45.475 h1.5
  text "3" at 107.475,43.375 h1.5
  text "2" at 107.475,41.425 h1.5
  text "1" at 107.425,39.425 h1.5
  text "CAN" at 105.35,36.55 h1.5 r270
  text "SWD" at 107.75,36.55 h1.5 r270
Mechanical 12:
  the board outline again, w0.2
Mechanical 14:
  text "2" at -26.3,-180.4 h5
Mechanical 15:
  lines w0.2: 110.925,53.275 113.125,53.275
RefDes_top_SB:
  drawing of 314 lines, arcs and shapes, not listed
  text "СИЭТ 21.02.110.000 СБ" at 42.7,98.6 h5 r180
  text "Top side components" at 40.575,81.825 h5
  text "2" at 119.863,55.525 h3.5
  text "1" at 119.863,49.565 h3.5
  text "Layer" at -0.426,-21.036 h2.5
  text "Name" at 9.986,-21.036 h2.5
  text "Material" at 33.601,-21.036 h2.5
  text "Thickness" at 55.439,-21.036 h2.5
  text "Constant" at 71.945,-21.036 h2.5
  text "Board Layer Stack" at 86.42,-21.036 h2.5
  text "1" at -0.426,-24.084 h2.5
  text "Top Overlay" at 9.986,-24.084 h2.5
  text "2" at -0.426,-27.132 h2.5
  text "Top Solder" at 9.986,-27.132 h2.5
  text "Solder Resist" at 33.601,-27.132 h2.5
  text "0,020mm" at 55.439,-27.132 h2.5
  text "3,5" at 71.945,-27.132 h2.5
  text "3" at -0.426,-30.18 h2.5
  text "Top Layer" at 9.986,-30.18 h2.5
  text "Copper" at 33.601,-30.18 h2.5
  text "0,035mm" at 55.439,-30.18 h2.5
  text "4" at -0.426,-33.236 h2.5
  text "Dielectric 1" at 9.986,-33.236 h2.5
  text "Prepreg FR-4" at 33.601,-33.236 h2.5
  text "0,320mm" at 55.439,-33.236 h2.5
  text "4,2" at 71.945,-33.236 h2.5
  text "5" at -0.426,-36.311 h2.5
  text "Mid Layer 1" at 9.986,-36.311 h2.5
  text "Copper" at 33.601,-36.311 h2.5
  text "0,035mm" at 55.439,-36.311 h2.5
  text "6" at -0.426,-39.361 h2.5
  text "Dielectric 2" at 9.986,-39.361 h2.5
  text "Core FR-4" at 33.601,-39.361 h2.5
  text "0,710mm" at 55.439,-39.361 h2.5
  text "4,2" at 71.945,-39.361 h2.5
  text "7" at -0.426,-42.398 h2.5
  text "Mid Layer 2" at 9.986,-42.398 h2.5
  text "Copper" at 33.601,-42.398 h2.5
  text "0,035mm" at 55.439,-42.398 h2.5
  text "8" at -0.426,-45.437 h2.5
  text "Dielectric 3" at 9.986,-45.437 h2.5
  text "Prepreg FR-4" at 33.601,-45.437 h2.5
  text "0,320mm" at 55.439,-45.437 h2.5
  text "4,2" at 71.945,-45.437 h2.5
  text "9" at -0.426,-48.485 h2.5
  text "Bottom Layer" at 9.986,-48.485 h2.5
  text "Copper" at 33.601,-48.485 h2.5
  text "0,035mm" at 55.439,-48.485 h2.5
  text "10" at -0.426,-51.533 h2.5
  text "Bottom Solder" at 9.986,-51.533 h2.5
  text "Solder Resist" at 33.601,-51.533 h2.5
  text "0,020mm" at 55.439,-51.533 h2.5
  text "3,5" at 71.945,-51.533 h2.5
  text "11" at -0.426,-54.581 h2.5
  text "Bottom Overlay" at 9.986,-54.581 h2.5
  text "1. * Reference dimensions." at -8.55,-65.15 h5
  text "2. To make installation of components according to the drawing and BOM:" at -8.55,-70.65 h5
  text "CB-2_v01c-BOM(2018.06.15).xls" at -4.3,-76.15 h5
  text "3. Elements for surface mountng should be mounted symmetrically to pads." at -8.55,-81.65 h5
  text "4. Elements position 1(R32), 2(R70), 3(R73), 4(C43), 5(C42), 7(FU1) do not install." at -8.55,-87.15 h5
  text "5. Element position 6(RT2) install at the level of" at -8.55,-92.65 h5
  text "the heat-conducting surface of Power Module (A1)." at -4.3,-98.15 h5
  text "6. Solder Sn60Pb40 or an analog in coordination with the producer." at -8.55,-103.65 h5
  text "Soldering paste N82CR32AgS59.5 (for SMD elements)." at -4.3,-109.15 h5
  text "7. Printing conductors aren't shown." at -8.55,-114.65 h5
  text "8. Designations of elements correspond to the scheme СИНТ ПУ 00.00.02.000 Э3." at -8.55,-120.15 h5
  text "СИЭТ 21.02.110.000 СБ" at 65.075,-137.85 h7
  text "Control Board" at 69.55,-148.7 h5
  text "(CB-2)" at 78.3,-155.9 h5
  text "Assembly Drawing" at 66.25,-163.7 h5
  text "2" at 158.5,-166.5 h3.5
RefDes_bot_SB:
  circle w0.25: c103.39,55.1 r0.25
  circle w0.25: c33.84,39.95 r0.25
  circle w0.25: c14.94,27.85 r0.25
  lines w0.2: 1.55,-5.7 4.95,-5.7 ; 4.971,-5.691 14.95,27.85 ; 17.227,-5.658 20.627,-5.658 33.85,39.95 ; 103.4,55.1 118.75,49.6 122.15,49.6
  text "СИЭТ 21.02.110.000 СБ" at 94.75,98.5 h5 r180
  text "Bottom side components" at 77.275,81.75 h5
  text "3" at 121.1,50.1 h3.5
  text "4" at 19.577,-5.158 h3.5
  text "5" at 3.9,-5.2 h3.5
  text "СИЭТ 21.02.110.000 СБ" at 65.725,-177.6 h7
A2_sh1_BrdTxt_2d1:
  lines w0.4: 135.15,0 135.15,69.95 136.65,69.95 136.65,0 135.15,0
  text "СИЭТ 21.02.110.001" at 38.5,98.5 h5 r180
  text "1. Плату печатную изготовить комбинированным негативным методом." at -8.55,-43.15 h5
  text "2. Плата должна соответствовать ГОСТ 23752-79, группа жесткости 3." at -8.55,-48.65 h5
  text "3. Класс точности 5 в соответствии с ГОСТ 23751-86." at -8.55,-54.15 h5
  text "4. Данные проектирования ПП в формате Altium Designer 9.1 ПУ-2_v02.PcbDoc." at -8.55,-59.65 h5
  text "Единицы измерения: мм." at -4.3,-65.15 h5
  text "5. Обозначения слоев показаны условно." at -8.55,-70.65 h5
  text "6. Материал диэлектрика FR-4 по IPC-4101." at -8.55,-76.15 h5
  text "7. Толщина слоя меди в отверстии не менее 20 мкм." at -8.55,-81.65 h5
  text "8. Паяльная маска по IPC-SM-840, цвет зеленый, тип жидкая." at -8.55,-87.15 h5
  text "Толщина покрытия не более 50 мкм." at -4.3,-92.65 h5
  text "9. Шелкография белая с диэлектрическими свойствами." at -8.55,-98.15 h5
  text "10. 100% тестирование на короткое замыкание и обрыв." at -8.55,-103.65 h5
  text "11. Контур платы обработать фрезой." at -8.55,-109.15 h5
  text "12. Предельные отклонения размеров +- IT12/2." at -8.55,-114.65 h5
  text "13. Маркировать заводской, технологический номер." at -8.55,-120.15 h5
  text "СИЭТ 21.02.110.001" at 70.025,-137.85 h7
  text "Плата печатная" at 66,-156 h5
  text "5" at 158.5,-166.5 h3.5
A2_sh2_mirr_BrdTxt_2d1:
  text "СИЭТ 21.02.110.001" at 97.5,98.5 h5 r180
  text "СИЭТ 21.02.110.001" at 62.325,-177.65 h7
  text "5" at -26.3,-180.4 h5
A2_sh2_mirr_2d1:
  lines w0.1: -37,-188 173,-188 173,109 -37,109 -37,-188
  lines w0.3: 88,-173 153,-173
  lines w0.75: -32,-175 -22,-175 ; -32,-168 153,-168 153,-183 -32,-183 -32,104 153,104 153,-183 165,-183 165,-38 153,-38 ; -22,-183 -22,-168 ; 83,104 83,90 153,90 ; 88,-183 88,-168 ; 88,-178 153,-178 ; 98,-183 98,-168 ; 113,-183 113,-168 ; 136,-183 136,-168 ; 146,-183 146,-168 ; 153,-158 165,-158 ; 153,-123 165,-123 ; 153,-98 165,-98 ; 153,-73 165,-73 ; 160,-183 160,-38
  text "Подп. и дата" at 161.5,-65 h3.5 r270
  text "Инв. № дубл." at 161.5,-94 h3.5 r270
  text "Взам. инв. №" at 161.5,-119.5 h3.5 r270
  text "Подп. и дата" at 161.5,-150.5 h3.5 r270
  text "Лист" at -23.75,-172.75 h3.5
  text "Инв. № подл." at 161.5,-178.5 h3.5 r270
  text "Дата" at 96.3,-181.5 h3.5
  text "Подп." at 108.6,-181.5 h3.5
  text "№ докум." at 130,-181.5 h3.5
  text "Лист" at 144.1,-181.5 h3.5
  text "Изм." at 152.1,-181.5 h3.5
  text "Формат А4" at -4,-186.5 h3.5
  text "Копировал" at 56,-186.5 h3.5
A2_sh1_2d1:
  lines w0.1: -37,-188 -37,109 173,109 173,-188 -37,-188
  lines w0.3: -17,-178 48,-178 ; -17,-173 48,-173 ; -17,-168 48,-168 ; -17,-163 48,-163 ; -17,-158 48,-158 ; -17,-143 48,-143 ; -17,-138 48,-138 ; -17,-133 48,-133 ; 123,-163 123,-148 ; 128,-163 128,-148
  lines w0.75: -29,-158 -17,-158 ; -29,-123 -17,-123 ; -29,-98 -17,-98 ; -29,-73 -17,-73 ; -29,104 -17,104 ; -29,44 -17,44 ; -29,104 -29,-16 -17,-16 ; -24,-183 -24,-38 ; -24,-16 -24,104 ; -17,-153 48,-153 ; -17,-148 48,-148 ; -17,-38 -29,-38 -29,-183 -17,-183 ; -17,90 53,90 53,104 ; -10,-153 -10,-128 ; 0,-183 0,-128 ; 23,-183 23,-128 ; 38,-183 38,-128 ; 48,-183 48,-128 ; 48,-168 168,-168 ; 48,-143 168,-143 ; 118,-183 118,-143 ; 118,-163 168,-163 ; 118,-148 168,-148 ; 133,-163 133,-143 ; 138,-168 138,-163 ; 150,-163 150,-143 ; 168,-128 -17,-128 -17,-183 ; -17,-183 168,-183 168,104 -17,104 ; -17,-183 -17,104
  text "Перв. примен." at -25.5,64 h3.5 r90
  text "Справ. №" at -25.5,9 h3.5 r90
  text "Подп. и дата" at -25.5,-65 h3.5 r90
  text "Инв. № дубл." at -25.5,-94 h3.5 r90
  text "Взам. инв. №" at -25.5,-119.5 h3.5 r90
  text "Лит." at 123,-146.5 h3.5
  text "Масса" at 138,-146.5 h3.5
  text "Масштаб" at 153,-146.5 h3.5
  text "Подп. и дата" at -25.5,-150.5 h3.5 r90
  text "Изм." at -16,-151.5 h3.5
  text "Лист" at -8.5,-151.5 h3.5
  text "№ докум." at 5.5,-151.5 h3.5
  text "Подп." at 27,-151.5 h3.5
  text "Дата" at 39.5,-151.5 h3.5
  text "Разраб." at -15.5,-156.5 h3.5
  text "Булычев" at 3,-156.5 h3.5
  text ".Print_Date" at 39.2,-156.5 h3.5
  text "1:1" at 158,-157 h3.5
  text "Пров." at -15.5,-161.5 h3.5
  text "Ермаков" at 3,-161.5 h3.5
  text "Т.контр." at -15.5,-166.5 h3.5
  text "Лист" at 121,-166.5 h3.5
  text "1" at 132,-166.5 h3.5
  text "Листов" at 141,-166.5 h3.5
  text "B&E" at 149.075,-176.025 h6
  text "Н.контр." at -15.5,-176.5 h3.5
  text "SINtech" at 122.925,-177.2 h6
  text "Инв. № подл." at -25.5,-178.5 h3.5 r90
  text "INVERTER" at 149.25,-179.2 h3
  text "Утв." at -15.5,-181.5 h3.5
  text "Булычев" at 3,-181.5 h3.5
  text "Копировал" at 80,-186.5 h3.5
  text "Формат А4" at 140,-186.5 h3.5
A2_sh2_2d1:
  lines w0.1: -37,-188 -37,109 173,109 173,-188 -37,-188
  lines w0.3: -17,-173 48,-173
  lines w0.75: -29,-158 -17,-158 ; -29,-123 -17,-123 ; -29,-98 -17,-98 ; -29,-73 -17,-73 ; -24,-183 -24,-38 ; -17,-178 48,-178 ; -17,-38 -29,-38 -29,-183 -17,-183 ; -17,90 53,90 53,104 ; -10,-183 -10,-168 ; 0,-183 0,-168 ; 23,-183 23,-168 ; 38,-183 38,-168 ; 48,-183 48,-168 ; 158,-183 158,-168 ; 158,-175 168,-175 ; 168,-168 -17,-168 -17,-183 ; -17,-183 -17,104 168,104 168,-183 -17,-183
  text "СИЭТ 21.02.110.001" at 38.5,98.5 h5 r180
  text "Подп. и дата" at -25.5,-65 h3.5 r90
  text "Инв. № дубл." at -25.5,-94 h3.5 r90
  text "Взам. инв. №" at -25.5,-119.5 h3.5 r90
  text "Подп. и дата" at -25.5,-150.5 h3.5 r90
  text "Лист" at 159.75,-172.75 h3.5
  text "СИЭТ 21.02.110.001" at 73.675,-177.65 h7
  text "Инв. № подл." at -25.5,-178.5 h3.5 r90
  text "Изм." at -16.1,-181.5 h3.5
  text "Лист" at -8.1,-181.5 h3.5
  text "№ докум." at 6,-181.5 h3.5
  text "Подп." at 27.4,-181.5 h3.5
  text "Дата" at 39.7,-181.5 h3.5
  text "Копировал" at 80,-186.5 h3.5
  text "Формат А4" at 140,-186.5 h3.5

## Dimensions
135.15,0 to 136.65,0 on Mechanical 16
135.15,0.55 to 136.65,0.55 on Mechanical 16
136.65,0.55 to 143.25,9 on Mechanical 16
135.1,69.35 to 130.068,61.463 on Mechanical 16
0,0 to 115,0 on Mechanical 11
0,0 to 0,70 on Mechanical 11
0,0 to 13,36 on Mechanical 11
4.5,0 to 50,22 on Mechanical 11
50,64 to 0,0 on Mechanical 11
0,0 to 13,36 on Mechanical 11
0,0 to 50,64 on Mechanical 11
